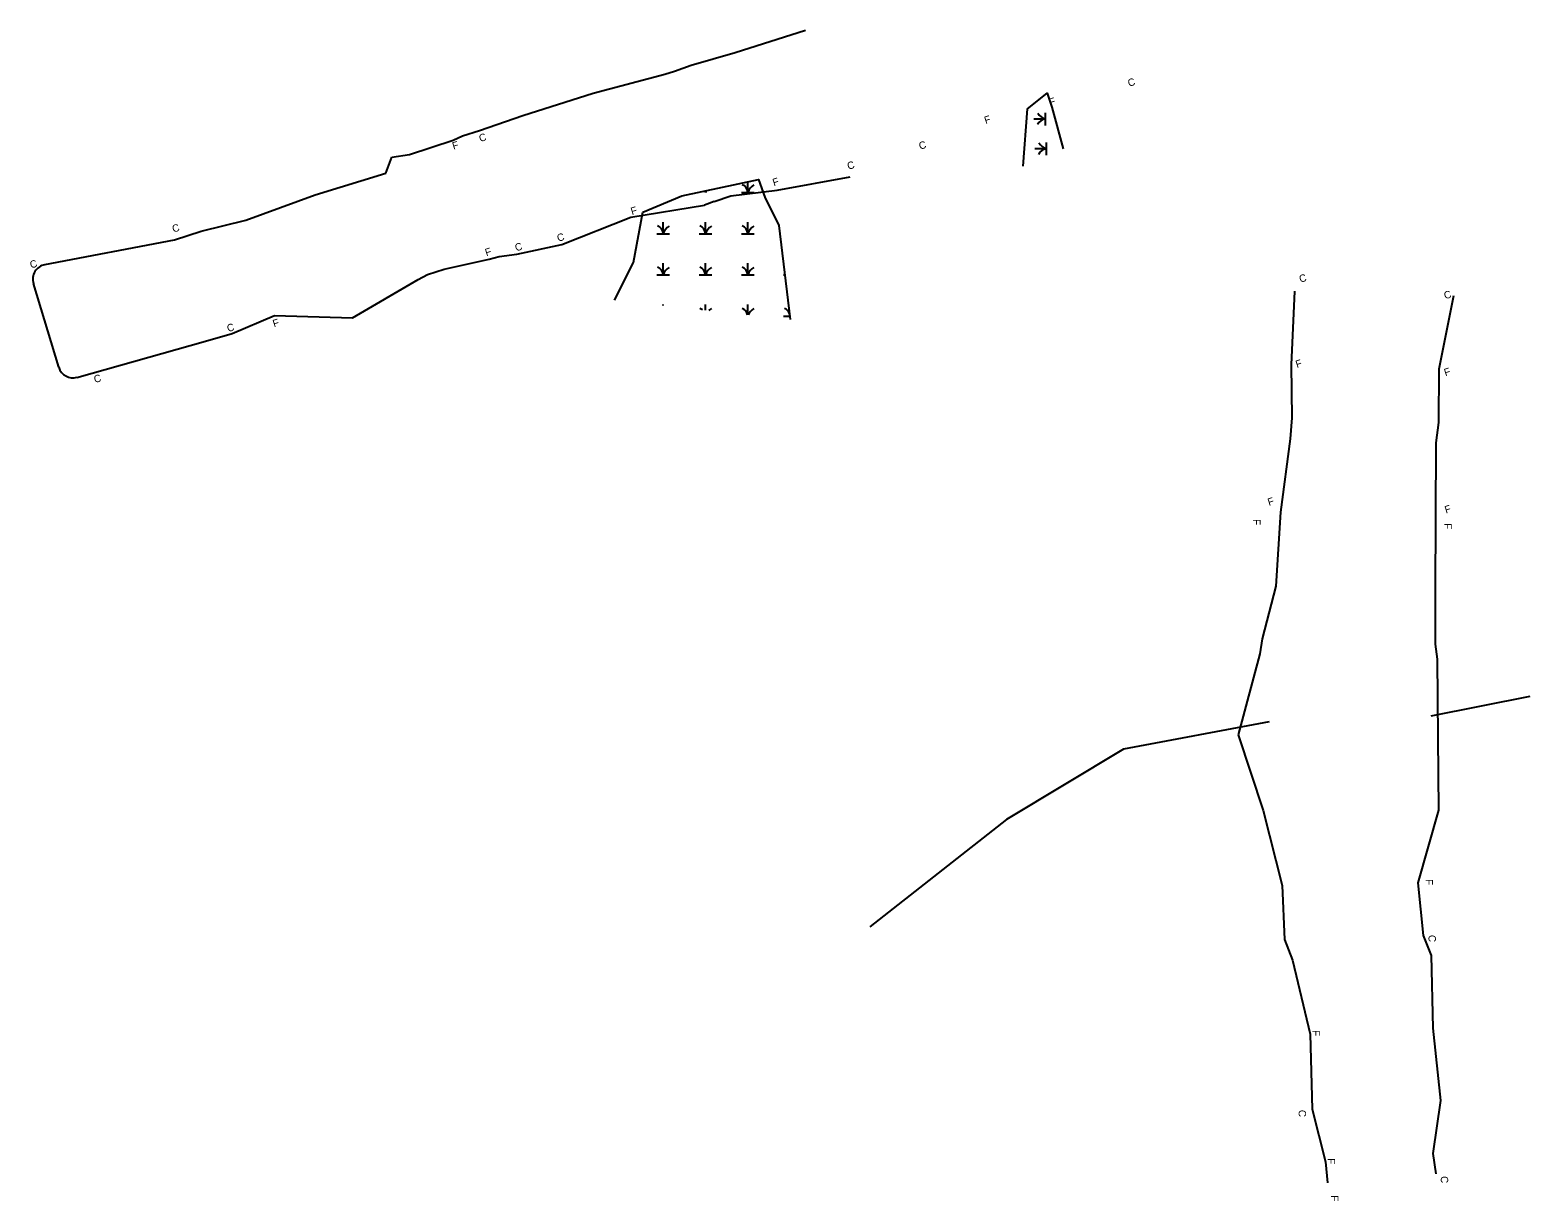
# Model space of a CAD drawing. Extents: x 2166958 to 2178986, y 64620 to 71122.
# Drawn here: x 2166958 to 2167973, y 64620 to 65412 of the extents above; entities that cross this region are included whole.
import ezdxf

# ---------------------------------------------------------------- set-up
doc = ezdxf.new("R2010")
doc.units = 0
for name, color, linetype in [('Default', 7, 'Continuous'), ('Prop Horizontal Alignment', 7, 'Continuous'), ('Prop Horizontal Alignment Station Label', 7, 'Continuous'), ('Prop Horizontal Alignment Tick Label', 7, 'Continuous')]:
    doc.layers.add(name, color=color, linetype=linetype)

# ---------------------------------------------------------------- blocks, each defined once
blk = doc.blocks.new('EXIST HYDRO SWAMP OR MARSH')
at = {"layer": 'Default'}
for p, q in [((0, -0.036), (0, 0.043)), ((0, 0), (0, 0)), ((-0.043, -0.036), (0.043, -0.036))]:
    blk.add_line(p, q, dxfattribs=at)
for centre, radius, start, end in [((-0.061, -0.04), 0.0615, 4.1403, 67.535), ((0.091, -0.066), 0.0961, 122.1274, 161.6222)]:
    blk.add_arc(centre, radius, start, end, dxfattribs=at)

msp = doc.modelspace()

# ---------------------------------------------------------------- linework, layer by layer
at = {"layer": 'Default'}
for p, q in [((2167435.5, 65397.3), (2167483.1, 65412.4)), ((2167405.7, 65388.7), (2167435.5, 65397.3)), ((2167339.4, 65369.6), (2167387.7, 65382.5)), ((2167387.7, 65382.5), (2167394.4, 65384.5)), ((2167394.4, 65384.5), (2167405.7, 65388.7)), ((2167291.6, 65354.7), (2167339.4, 65369.6)), ((2167262.3, 65344.5), (2167291.6, 65354.7)), ((2167250.9, 65340.8), (2167262.3, 65344.5)), ((2167215, 65328.3), (2167244.5, 65337.8)), ((2167244.5, 65337.8), (2167250.9, 65340.8)), ((2167199, 65315.6), (2167203.1, 65326.3)), ((2167203.1, 65326.3), (2167215, 65328.3)), ((2167151.2, 65301), (2167199, 65315.6)), ((2167463.8, 65304.1), (2167513.3, 65313.1)), ((2167432.5, 65300.2), (2167463.8, 65304.1)), ((2167104.2, 65283.7), (2167151.2, 65301)), ((2167364.8, 65285.9), (2167414.6, 65293.9)), ((2167421.2, 65296.3), (2167414.6, 65293.9)), ((2167421.2, 65296.3), (2167432.5, 65300.2)), ((2167074, 65276.3), (2167104.2, 65283.7)), ((2167318.1, 65267.4), (2167364.8, 65285.9)), ((2167055.9, 65270.5), (2167074, 65276.3)), ((2166968.1, 65253.7), (2167055.9, 65270.5)), ((2167275.7, 65259.2), (2167287.7, 65260.8)), ((2167287.7, 65260.8), (2167318.1, 65267.4)), ((2167227.1, 65247.1), (2167238.5, 65250.7)), ((2167238.5, 65250.7), (2167268.9, 65257.4)), ((2167268.9, 65257.4), (2167275.7, 65259.2)), ((2166977.6, 65184.2), (2166960.4, 65240.9)), ((2167176.4, 65217.7), (2167220.8, 65243.6)), ((2167220.8, 65243.6), (2167227.1, 65247.1)), ((2167813.9, 65235.8), (2167811.7, 65185.9)), ((2167921.5, 65232.6), (2167911.7, 65182.9)), ((2167095, 65207), (2167123.7, 65219.3)), ((2167123.7, 65219.3), (2167176.4, 65217.7)), ((2166989.9, 65177.4), (2167076.8, 65201.8)), ((2167076.8, 65201.8), (2167095, 65207)), ((2167811.7, 65185.9), (2167812.1, 65149.9)), ((2167911.7, 65182.9), (2167911.5, 65146.9)), ((2167812.1, 65149.9), (2167811, 65135.9)), ((2167911.5, 65146.9), (2167909.7, 65133)), ((2167811, 65135.9), (2167804.5, 65086.1)), ((2167909.7, 65133), (2167909.5, 65082.9)), ((2167804.5, 65086.1), (2167801.3, 65036.1)), ((2167909.5, 65082.9), (2167909.2, 65032.9)), ((2167801.3, 65036.1), (2167792, 65000.4)), ((2167909.2, 65032.9), (2167909.1, 64996.9)), ((2167792, 65000.4), (2167790.6, 64990.2)), ((2167909.1, 64996.9), (2167910.5, 64986.6)), ((2167790.6, 64990.2), (2167775.9, 64935.5)), ((2167910.5, 64986.6), (2167911.1, 64933.8)), ((2167775.9, 64935.5), (2167792.7, 64884.3)), ((2167911.1, 64933.8), (2167911.5, 64884.6)), ((2167792.7, 64884.3), (2167805.7, 64833.6)), ((2167911.5, 64884.6), (2167897.4, 64835.3)), ((2167897.4, 64835.3), (2167901, 64799.8)), ((2167805.7, 64833.6), (2167807.3, 64797.1)), ((2167807.3, 64797.1), (2167812.7, 64783)), ((2167901, 64799.8), (2167906.6, 64786.2)), ((2167906.6, 64786.2), (2167907.6, 64737)), ((2167812.7, 64783), (2167824.5, 64732.9)), ((2167824.5, 64732.9), (2167826, 64682.3)), ((2167907.6, 64737), (2167912.7, 64688)), ((2167826, 64682.3), (2167834.9, 64646.5)), ((2167912.7, 64688), (2167907.7, 64652.1)), ((2167907.7, 64652.1), (2167909.6, 64638.4)), ((2167834.9, 64646.5), (2167836.3, 64632.4))]:
    msp.add_line(p, q, dxfattribs=at)
for centre, start, end in [((2166970, 65243.8), 100.8477, 196.8869), ((2166987.2, 65187.1), 196.8869, 285.6662)]:
    msp.add_arc(centre, 10, start, end, dxfattribs=at)
at = {"layer": 'Prop Horizontal Alignment'}
for points in [[(2167630.3, 65320.2), (2167633.2, 65359.2), (2167646.5, 65369.6), (2167649.8, 65360.2), (2167657.3, 65332)], [(2167353.8, 65229.6), (2167366.6, 65255.2), (2167372.9, 65289.2), (2167399.4, 65300.2), (2167451.2, 65311.2), (2167455.4, 65299.4), (2167464.9, 65280.2), (2167472.7, 65216.5)]]:
    msp.add_lwpolyline(points, dxfattribs=at)
at = {"layer": 'Prop Horizontal Alignment Station Label'}
for p, q in [((2167439.6, 65302.5), (2167448.2, 65302.5)), ((2167443.9, 65302.5), (2167443.9, 65309.7)), ((2167386.7, 65274.6), (2167386.7, 65282.5)), ((2167415.3, 65274.6), (2167415.3, 65282.5)), ((2167443.9, 65274.6), (2167443.9, 65282.5)), ((2167382.4, 65274.6), (2167391, 65274.6)), ((2167411, 65274.6), (2167419.6, 65274.6)), ((2167439.6, 65274.6), (2167448.2, 65274.6)), ((2167386.7, 65246.7), (2167386.7, 65254.6)), ((2167415.3, 65246.7), (2167415.3, 65254.6)), ((2167443.9, 65246.7), (2167443.9, 65254.6)), ((2167362.4, 65246.7), (2167362.4, 65246.7)), ((2167382.4, 65246.7), (2167391, 65246.7)), ((2167411, 65246.7), (2167419.6, 65246.7)), ((2167439.6, 65246.7), (2167448.2, 65246.7)), ((2167468.2, 65246.7), (2167469, 65246.7)), ((2167386.7, 65226), (2167386.7, 65226.7)), ((2167415.3, 65222.8), (2167415.3, 65226.7)), ((2167443.9, 65219.7), (2167443.9, 65226.7)), ((2167468.2, 65218.8), (2167472.4, 65218.8))]:
    msp.add_line(p, q, dxfattribs=at)
for centre, radius, start, end in [((2167409.2, 65302.1), 6.15, 4.1403, 13.8058), ((2167424.4, 65299.5), 9.61, 154.1633, 161.6222), ((2167437.8, 65302.1), 6.15, 4.1403, 67.535), ((2167453.1, 65299.5), 9.61, 122.1274, 161.6222), ((2167380.6, 65274.2), 6.15, 4.1403, 67.535), ((2167395.8, 65271.6), 9.61, 122.1274, 161.6222), ((2167409.2, 65274.2), 6.15, 4.1403, 67.535), ((2167424.4, 65271.6), 9.61, 122.1274, 161.6222), ((2167437.8, 65274.2), 6.15, 4.1403, 67.535), ((2167453.1, 65271.6), 9.61, 122.1274, 161.6222), ((2167380.6, 65246.3), 6.15, 4.1403, 67.535), ((2167395.8, 65243.7), 9.61, 122.1274, 161.6222), ((2167409.2, 65246.3), 6.15, 4.1403, 67.535), ((2167424.4, 65243.7), 9.61, 122.1274, 161.6222), ((2167437.8, 65246.3), 6.15, 4.1403, 67.535), ((2167453.1, 65243.7), 9.61, 122.1274, 161.6222), ((2167409.2, 65218.4), 6.15, 49.0218, 67.535), ((2167424.4, 65215.8), 9.61, 122.1274, 135.423), ((2167437.8, 65218.4), 6.15, 11.8932, 67.535), ((2167453.1, 65215.8), 9.61, 122.1274, 156.6587), ((2167466.4, 65218.4), 6.15, 18.6048, 67.535)]:
    msp.add_arc(centre, radius, start, end, dxfattribs=at)
at = {"layer": 'Prop Horizontal Alignment Tick Label'}
msp.add_line((2167906.4, 64948.4), (2167973.4, 64961.7), dxfattribs=at)
msp.add_lwpolyline([(2167796.8, 64944.4), (2167698.2, 64925.7), (2167619.1, 64878.1), (2167526.5, 64805.6)], dxfattribs=at)

# ---------------------------------------------------------------- block references
at = {"layer": 'Prop Horizontal Alignment Station Label', "xscale": 99.99980000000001, "yscale": 99.99980000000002, "rotation": 90}
for p in [(2167641.8, 65352.2), (2167642.5, 65332)]:
    msp.add_blockref('EXIST HYDRO SWAMP OR MARSH', p, dxfattribs=at)

# ---------------------------------------------------------------- texts
at = {"layer": 'Default'}
for s, rotation, p in [('C', 17.1823, (2167702, 65374)), ('F', 17.1823, (2167648.8, 65361)), ('F', 17.1823, (2167604.9, 65348.8)), ('C', 17.1823, (2167262.9, 65336.6)), ('F', 17.1823, (2167244.8, 65331.4)), ('C', 17.1823, (2167560.6, 65331.4)), ('C', 17.1823, (2167512.1, 65317.8)), ('F', 17.1823, (2167461.6, 65306.7)), ('F', 17.1823, (2167365.6, 65287.2)), ('C', 17.1823, (2167055.2, 65275.3)), ('C', 17.1823, (2167315.7, 65269.1)), ('F', 17.1823, (2167267, 65259.3)), ('C', 17.1823, (2167287.2, 65262.6)), ('C', 17.1823, (2166958.9, 65251)), ('C', 17.1823, (2167818, 65241.4)), ('C', 17.1823, (2167916, 65230.2)), ('C', 17.1823, (2167092.3, 65208)), ('F', 17.1823, (2167123.3, 65211.2)), ('F', 17.1823, (2167815.6, 65183.7)), ('C', 17.1823, (2167002.2, 65173.5)), ('F', 17.1823, (2167916.1, 65178.1)), ('F', 17.1823, (2167796.7, 65090.4)), ('F', 17.1823, (2167916.5, 65085.2)), ('F', 269.9291, (2167786, 65081.5)), ('F', 269.9291, (2167915.4, 65078.7)), ('F', 269.9291, (2167902.7, 64837.9)), ('C', 269.9291, (2167904.7, 64800.1)), ('F', 269.9291, (2167826.1, 64735.7)), ('C', 269.9291, (2167816.8, 64681.7)), ('F', 269.9291, (2167836.4, 64649)), ('C', 269.9291, (2167913, 64636.9)), ('F', 269.9291, (2167838.7, 64623.9))]:
    msp.add_text(s, height=5, rotation=rotation, dxfattribs=at).set_placement(p)

doc.saveas('drawing.dxf')
